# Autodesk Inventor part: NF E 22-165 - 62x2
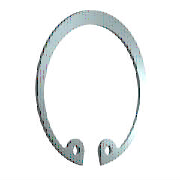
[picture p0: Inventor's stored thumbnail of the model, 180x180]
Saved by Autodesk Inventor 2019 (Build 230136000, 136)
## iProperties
Created: 2018-01
Part Number: NF E 22-165 - 62x2
Material: Acier, doux
Description: Rondelle élastique d´arrêt
Document SubType Name: Modeling
Standard: NF E 22-165
Designer: SI
Standards Organization: AFNOR
Language: fr-FR
Size Designation: 62x2
Categories: <MemberInstance><Categories><Category DisplayName="Pièces d'arbre" InternalName="7f7aeb1f-a693-4053-b835-cee3144e0d98" Mnemonic="SHFT"><Category DisplayName="An
Density: 7.85 g/cm^3
Appearance: Semi-poli
IsCustomPart: 0
Author: SI
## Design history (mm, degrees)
sketch "Esquisse1"
  geometry: L1 (0, 15.113)-(0, -73.177) reference; L2 (-45.5, 0)-(45.5, 0) reference; L3 (-4.964, 2.5)-(1.502, 2.5); L4 (0, -3)-(-5.307, -3); L5 (0, -30)-(-13.368, -59.623); L6 (-13.368, -59.623)-(-26.939, -53.499); L7 (-11.867, -56.296)-(-22.418, -51.535); L8 (-9.588, -57.325)-(-11.05, -60.564); L9 (9.588, -57.325)-(11.05, -60.564); C1 r 1.25 at (-11.867, -56.296); C2 r 1.25 at (11.867, -56.296); A1 r 28.375 centre (0, -31.375) between (16.492, -54.465) and (-16.492, -54.465); A2 r 32.5 centre (0, -30) between (11.05, -60.564) and (-11.05, -60.564); A3 r 2.5 centre (-11.867, -56.296) between (-9.588, -57.325) and (-13.453, -54.364); A4 r 2.5 centre (-15.039, -52.431) between (-16.492, -54.465) and (-13.453, -54.364); A5 r 2.5 centre (15.039, -52.431) between (13.453, -54.364) and (16.492, -54.465); A6 r 2.5 centre (11.867, -56.296) between (13.453, -54.364) and (9.588, -57.325); 3 further points
  constraints: 15 point on circle, 14 end point, 9 symmetric about line, 8 centre point, 6 tangent, 4 coincident, 4 point on line, 3 perpendicular, 1 parallel, 4 other
  dimensions: "d8" = 1.375 distance of A1.centre L5.start (= 0.25 x SRB1); "d38" = 5.5 distance between parallel lines of L4 L3 (= SRB1); "d39" = 30 distance from line of L5.start L2 (= 0.5 x WD); "d43" = 32.5 radius of A2 (= 0.5 x ND); "d45" = 3.65 distance between parallel lines of L7 L6 (= 0.5 x SRB2); "d46" = 2.5 radius of A4 (= SD5); "d47" = 11.05 distance from line of L1 L8.end (= 0.17 x ND); "d48" = 2.5 diameter of C1 (= SD5); "d49" = 2.5 radius of A3 (= SD5)
extrude "Corps" new body sketch "Esquisse1" distance "d2" = 2 (= SD); taper "d3" = 0 deg
workaxis "Work Axis1"
workaxis "Work Axis2"
workplane "Work Plane1"
body "Solid1"
other parameters: "SD" = 2 [user parameter; used in 1 equation term], "SRB1" = 5.5 [user parameter; used in 2 equation terms], "ND" = 65 [user parameter; used in 2 equation terms], "SRB2" = 7.3 [user parameter; used in 1 equation term], "SD5" = 2.5 [user parameter; used in 3 equation terms], "d50" = 0, "d51" = 0, "d52" = 0, "d53" = 0, "SD6" = 66.2 [user parameter], "NND" = 62 [user parameter; used in 1 equation term], "WDMAX" = 62 (= NND) [user parameter]
